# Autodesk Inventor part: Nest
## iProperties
Created: 2006-12
Part Number: Nest
Document SubType Name: Modeling
Designer: RDGodetteII
Material: Steel, Mild
Mass: 138806 g
Surface Area: 15202.9 cm^2
Volume: 17659.8 cm^3
Density: 7.86 g/cm^3
Author: RDGodetteII
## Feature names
1. Extrusion1
2. Fillet1
3. Hole1
4. Hole2
5. Hole3
